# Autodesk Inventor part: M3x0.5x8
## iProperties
IsCustomPart: 1
Company: 한국ATC센터
Created: 2009-02
Part Number: M3x0.5x8
Material: 강, 연강
Description: 6각머리 태핑 나사
Document SubType Name: Modeling
Standard: KS B 1003
Designer: KYOUNG IL JANG
Standards Organization: KS
Language: ko-KR
Size Designation: M 4 x 16
Categories: <MemberInstance><Categories><Category DisplayName="조임쇠" InternalName="e4da775c-781d-43d5-af7c-5136215cf5a6" Mnemonic="FSTN"><Category DisplayName="볼트" InternalN
Density: 7.86 g/cm^3
Mass: 2.43327 g
Surface Area: 3.56234 cm^2
Volume: 0.309576 cm^3
Vendor: CBT Solutions
Author: KYOUNG IL JANG
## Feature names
1. Fillet2
